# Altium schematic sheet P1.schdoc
size 297 x 209 mm; Symbol: Drawing-Symbol_A4; Company: 嘉立创EDA; Version: V1.0; Page Size: A4; @Project Name: esp32-c3-homekey+pen532; @Update Date: 2026-04-17; @Create Date: 2026-04-17; Device: Drawing-Symbol_A4; @Board Name: Board1; @Page Name: P1; @Create Time: 11:52:20; @Page Count: 1; @Page No: 1; @Schematic Name: Schematic1; @Update Time: 11:52:20; @Assembly Variant: Basic; Border: 1; Title Block Position: 3; Size: A4; Width: 1170; Height: 825; Region Start: 1; X Region Count: 6; Y Region Count: 4; Blade Width: 10; Title Block: 1
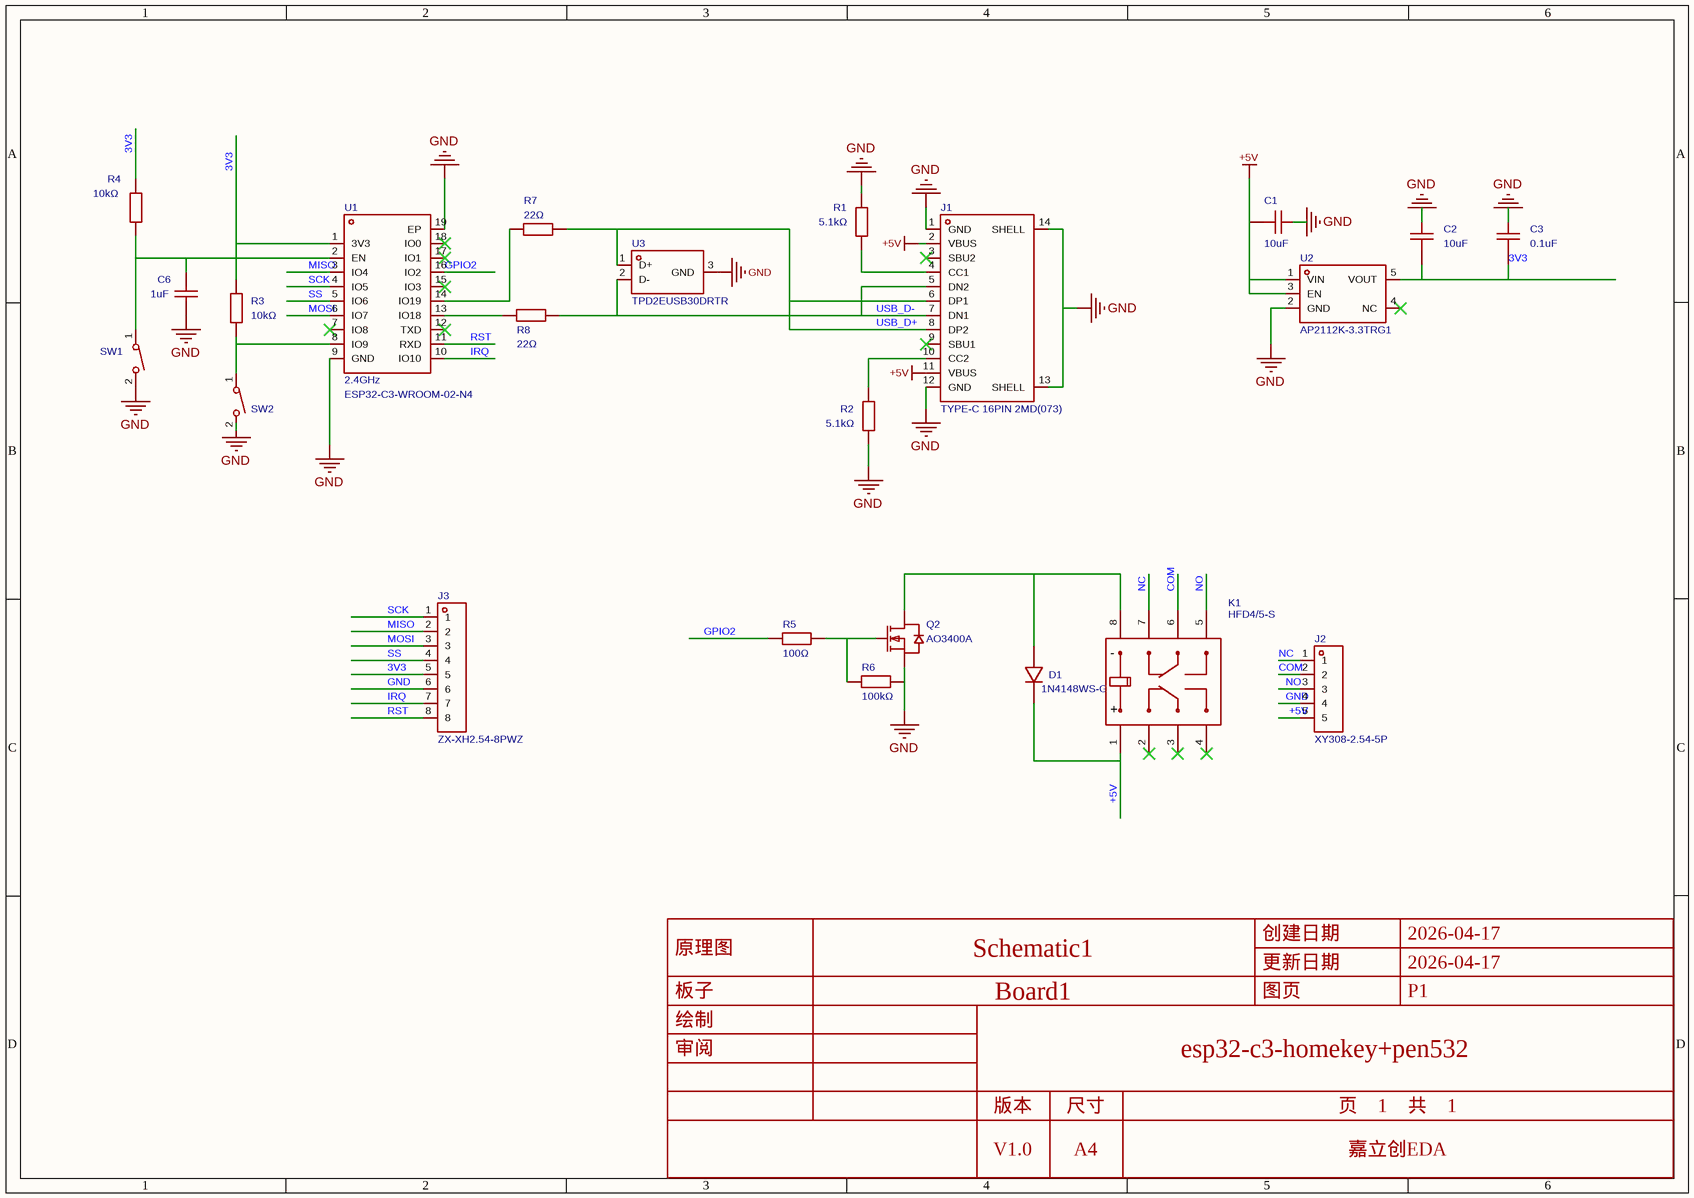
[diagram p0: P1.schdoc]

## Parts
C1  10uF  [C0805]
C2  10uF  [C0805]
C3  0.1uF  [C0805]
C6  1uF  [C0805]
D1  1N4148WS-G  [SOD-323_L1.7-W1.3-LS2.7-RD]
J1  TYPE-C 16PIN 2MD(073)  [USB-C-SMD_TYPE-C-6PIN-2MD-073]
J2  XY308-2.54-5P  [CONN-TH_XY308-2.54-5P]
J3  ZX-XH2.54-8PWZ  [CONN-TH_8P-P2.50_ZX-XH2.54-8PWZ]
K1  HFD4/5-S  [RELAY-SMD_HFD4-5-S]
Q2  AO3400A  [SOT-23-3_L2.9-W1.3-P1.90-LS2.4-BR]
R1  5.1kΩ  [R0805]
R2  5.1kΩ  [R0805]
R3  10kΩ  [R0805]
R4  10kΩ  [R0805]
R5  100Ω  [R0805]
R6  100kΩ  [R0805]
R7  22Ω  [R0603]
R8  22Ω  [R0603]
SW1  HX 3x4x2-2P-1.6N TACTILE SWITCH  [KEY-SMD_L4.0-W3.0-LS4.9-1]  (value not drawn)
SW2  HX 3x4x2-2P-1.6N TACTILE SWITCH  [KEY-SMD_L4.0-W3.0-LS4.9-1]  (value not drawn)
U1  2.4GHz  [BULETM-SMD_ESPRESSIF_ESP32-C3-WROOM-02-N4-4MB]
U2  AP2112K-3.3TRG1  [SOT-23-5_L2.9-W1.6-P0.95-LS2.8-BR]
U3  TPD2EUSB30DRTR  [SOT-723_L1.2-W0.8-P0.80-LS1.2-BR]

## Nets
+5V: C1.2 D1.1(-) J1.2(VBUS) J1.11(VBUS) J2.5 K1.1 U2.1(VIN) U2.3(EN)
GND: C1.1 C2.2 C3.1 C6.1 J1.1(GND) J1.12(GND) J1.13(SHELL) J1.14(SHELL) J2.4 J3.6 Q2.2(S) R1.2 R2.2 R6.2 SW1.2 SW2.2 U1.9(GND) U1.19(EP) U2.2(GND) U3.3(GND)
3V3: C2.1 C3.2 J3.5 R3.2 R4.2 U1.1(3V3) U2.5(VOUT)
COM: J2.2 K1.6
GPIO2: R5.1 U1.16(IO2)
IRQ: J3.7 U1.10(IO10)
MISO: J3.2 U1.3(IO4)
MOSI: J3.3 U1.6(IO7)
NC: J2.1 K1.7
NO: J2.3 K1.5
RST: J3.8 U1.11(RXD)
SCK: J3.1 U1.4(IO5)
SS: J3.4 U1.5(IO6)
USB_D+: J1.6(DP1) J1.8(DP2) R7.2 U3.1(D+)
USB_D-: J1.5(DN2) J1.7(DN1) R8.2 U3.2(D-)
NetC6_2: C6.2 R4.1 SW1.1 U1.2(EN)
NetD1_2: D1.2(+) K1.8 Q2.3(D)
NetJ1_4: J1.4(CC1) R1.1
NetJ1_10: J1.10(CC2) R2.1
NetQ2_1: Q2.1(G) R5.2 R6.1
NetR3_1: R3.1 SW2.1 U1.8(IO9)
NetR7_1: R7.1 U1.14(IO19)
NetR8_1: R8.1 U1.13(IO18)

Not connected (* = marked no-connect by the designer): J1 3(SBU2)* 9(SBU1)*; K1 2* 3* 4*; U1 7(IO8)* 12(TXD)* 15(IO3)* 17(IO1)* 18(IO0)*; U2 4(NC)*

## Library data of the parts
C1-C3 = CL21A106KAYNNNE_C15850: 容值:10uF;精度:±10%;额定电压:25V;温度系数:X5R;; Manufacturer: SAMSUNG(三星); 3D Model: 1ba041120af144c991958decab20d241; 3D Model Transform: 78.74,51.181,0,0,0,0,0,0.0005,0; Tolerance: ±10%; Voltage Rating: 25V; Temperature Coefficient: X5R; AddInBom: yes; ModelName: C0805_L2.0-W1.3-H1.3
C6 = CL21B105KBFNNNE: 容值:1uF;精度:±10%;额定电压:50V;温度系数:X7R;; Manufacturer: SAMSUNG(三星); 3D Model: 1ba041120af144c991958decab20d241; 3D Model Transform: 78.74,51.181,0,0,0,0,0,0.0005,0; Tolerance: ±10%; Voltage Rating: 50V; Temperature Coefficient: X7R; AddInBom: yes; ModelName: C0805_L2.0-W1.3-H1.3
D1 = 1N4148WS-G: 二极管配置:独立式;正向压降(Vf):1.25V@150mA;直流反向耐压(Vr):100V;整流电流:150mA;反向恢复时间(Trr):4ns;; Manufacturer: CJ(江苏长电/长晶); AddInBom: yes; ModelId: cb3f162a5497409a8a6cf33769e88f040819f05c4eef4c71ace90d822a990e87; ModelTransform: 102.362,50.197,0,0,0,0,0,0,0; Diode Configuration: 独立式; Voltage - DC Reverse(Vr): 100V; Current - Rectified: 150mA; Pd - Power Dissipation: 200mW; Reverse Leakage Current (Ir): 1uA@75V; Reverse Recovery Time (trr): 4ns; Non-Repetitive Peak Forward Surge Current: 2A
J1 = TYPE-C 16PIN 2MD(073): 连接器类型:Type-C;协议标准:-;公母:母;安装方式:卧贴;触点数量:16P;端口数量:1;额定电流 - 电源:3A;工作温度:-25℃~+85℃;; Manufacturer: SHOU HAN(首韩); 3D Model: 3a41b9ec9b654a0fad4d118405ec6290; 3D Model Transform: 351.9678,298.4246,0,0,0,0,0,-47.244,-35.433; Gender: 母; Number of Contacts: 16P; Number of Ports: 1; Current Rating-Power: 3A; Voltage Rating: 5V; Connect-Disconnect Life: 5千次; Detection color: 黑色; AddInBom: yes
J2 = XY308-2.54-5P: 结构:1x5P;间距:2.54mm;颜色:绿色;安装方式:直插;排数:1;每排PIN数:5;额定电流:6A;额定电压:150V;线规 - AWG:18~26;线规 - 平方毫米:1;工作温度:-;; Manufacturer: XINLAIYA(新莱亚); Add into BOM: yes; 3D Model: 19a24be1acf7462ab4ffe2d39b33f1bc; 3D Model Transform: 519.68794,255.905,0,0,0,0,0,-6.457,-137.795; Number of Positions or Pins: 1x5P; Pitch: 2.54mm; Number of PINs Per Row: 5; Screw Specification: M1.6; Current Rating: 6A; Voltage Rating (Max): 150V; Wire Gauge - AWG: 18~26; Wire Gauge - mm2: 1
J3 = ZX-XH2.54-8PWZ: 插针结构:1x8P;间距:2.5mm;安装方式:弯插;参考系列:XH;总PIN数:8P;排数:1;每排PIN数:8;行距:-;额定电流:3A;触头材质:黄铜;触头镀层:锡;工作温度:-25℃~+85℃;; Manufacturer: Megastar(兆星); AddInBom: yes; ModelId: 2313deb9a1954eec88de97710f9a8a070819f05c4eef4c71ace90d822a990e87; ModelTransform: 886.2187,300.7868,0,0,0,0,-0.002,-137.795,-133.858; Pins Structure: 1x8P; Pitch: 2.5mm; Reference Series: XH; Number of PINs Per Row: 8; Current Rating: 3A; Voltage Rating: 250V; Plastic Material: PA66; Flame Retardant Rating: UL94V-0; Z-Height of the Board: 5.9mm; X-Length of Bottom Edge on Board (Spacing Line): 22.5mm; Y-Width of Bottom Edge on Board: 7.32mm
K1 = HFD4/5-S: 线圈电压:5V;触点形式:两组转换:2C(双刀双掷-转换);触点容量(电阻负载):300mA@125VAC；1A@30VDC;最大切换电压:250V@AC；220V@DC;最大切换电流:2A;; Manufacturer: HF(宏发); Symbol: HFD4/5-S_C425975; AddInBom: yes; ModelId: 3a4f29bb16e8421f8a945af812fde40b0819f05c4eef4c71ace90d822a990e87; ModelName: SMD-8_L10.0-W6.5-H5.4-LS7.8-P2.2-3.2; ModelTransform: 393.7,307.086,0,0,0,0,0,0,0; Coil Voltage: 5V; Coil Rated Power: 140mW; Coil Resistance: 178Ω; Switching Current(Max): 2A; Operate Time: 3ms; Coil Type: 有极性-单线圈; Contact Resistance: 100mΩ
Q2 = AO3400A_C347475: 数量:1个N沟道;漏源电压(Vdss):30V;连续漏极电流(Id):5.8A;导通电阻(RDS(on)):17mΩ@10V;耗散功率(Pd):1.4W;阈值电压(Vgs(th)):1.1V@250uA;; Manufacturer: UMW(友台半导体); 3D Model: c62791f0466c4ae2a892c056b845b0ca; 3D Model Transform: 98.425,114.173,0,180,0,0,0.0005,-0.0005,0; Number: 1个N沟道; Drain to Source Voltage: 30V; Current - Continuous Drain(Id): 5.8A; Pd - Power Dissipation: 1.4W; Gate Charge(Qg): 9.7nC@4.5V; Input Capacitance(Ciss): 823pF; Reverse Transfer Capacitance (Crss@Vds): 77pF; Output Capacitance(Coss): 99pF; AddInBom: yes; ModelName: SOT-23-3P_L2.9-W1.3-H1.0-LS2.4-P0.95
R1 R2 = 0805W8F5101T5E: 电阻类型:厚膜电阻;阻值:5.1kΩ;精度:±1%;功率:125mW;工作电压:150V;温度系数:±100ppm/℃;; Manufacturer: UNI-ROYAL(厚声); 3D Model: 37a81e68749a4138bd2dfa6897b24b85; 3D Model Transform: 78.74,51.181,0,0,0,0,0,-0.0005,0; Tolerance: ±1%; Power(Watts): 125mW; Voltage-Supply(Max): 150V; AddInBom: yes; ModelName: R0805_L2.0-W1.3-H0.6
R3 R4 = 0805W8F1002T5E_C17414: 电阻类型:厚膜电阻;阻值:10kΩ;精度:±1%;功率:125mW;工作电压:150V;温度系数:±100ppm/℃;; Manufacturer: UNI-ROYAL(厚声); 3D Model: 37a81e68749a4138bd2dfa6897b24b85; 3D Model Transform: 78.74,51.181,0,0,0,0,0,-0.0005,0; Tolerance: ±1%; Power(Watts): 125mW; Voltage-Supply(Max): 150V; AddInBom: yes; ModelName: R0805_L2.0-W1.3-H0.6
R5 R6 = 0805W8F1003T5E: 电阻类型:厚膜电阻;阻值:100kΩ;精度:±1%;功率:125mW;工作电压:150V;温度系数:±100ppm/℃;; Manufacturer: UNI-ROYAL(厚声); Symbol: 0805W8F1003T5E_C149504; 3D Model: 37a81e68749a4138bd2dfa6897b24b85; 3D Model Transform: 78.74,51.181,0,0,0,0,0,-0.0005,0; Tolerance: ±1%; Power(Watts): 125mW; Voltage-Supply(Max): 150V; AddInBom: yes; ModelName: R0805_L2.0-W1.3-H0.6
R7 R8 = 0603WAF220JT5E: 电阻类型:厚膜电阻;阻值:22Ω;精度:±1%;功率:100mW;最大工作电压:75V;温度系数:±100ppm/℃;; Manufacturer: UNI-ROYAL(厚声); 3D Model: fc143cca1e79419f9cd78b61e9279f08; 3D Model Transform: 31.8897,63.7794,0,90,0,0,0,0,0; Tolerance: ±1%; Power(Watts): 100mW; Overload Voltage (Max): 75V; AddInBom: yes
SW1 SW2 = HX 3x4x2-2P-1.6N TACTILE SWITCH: 电路结构:单刀单掷;按钮形状:圆形按钮;作用力:1.6N;安装方式:立贴;开关长度:4mm;开关宽度:3mm;开关高度:2mm;带支架:不带支架;触点电流:50mA;额定电压:12V;带灯:无;工作寿命:10万次;; Manufacturer: hanxia(韩下); 3D Model: d4fce36ee1a0417eaaf0fe72bc7ffd98; 3D Model Transform: 188.976,114.173,0,0,0,0,0,0,-17.717; Circuit: 单刀单掷; Actuator Style: 圆形按钮; Operating Force: 1.6N; Switch Height: 2mm; with Bracket: 不带支架; Contact Current: 50mA; Voltage Rating: 12V; Actuator/Cap Color: 黑色; With Lamp: 无; Life: 10万次; AddInBom: yes; ModelName: KEY-SMD_L4.0-W3.0-LS4.9
U1 = ESP32-C3-WROOM-02-N4: 核心芯片:ESP32-C3芯片;频率:2.4GHz;天线形式:板载PCB天线;发射功率:20.5dBm;接收灵敏度:-105dBm;; Manufacturer: ESPRESSIF(乐鑫); Symbol: ESP32-C3-WROOM-02-N4(4MB); 3D Model: b84a3a07460a410dbd2d87addaa4e9c5; 3D Model Transform: 709.4474,787.4,0,0,0,0,-0.001,122.048,0; Wireless Standard: Bluetooth5.0; Interface Type: I2S；I2C；JTAG；UART；USB；SPI; Voltage - Supply: 3V~3.6V; Receive  Current: 82mA; Send  Current: 345mA; AddInBom: yes
U2 = AP2112K-3.3TRG1_C23380830: 输出类型:固定;工作电压:5.5V;输出电压:3.3V;输出电流:600mA;电源纹波抑制比(PSRR):75dB@(1kHz);输出极性:正极;; Manufacturer: TECH PUBLIC(台舟); 3D Model: 7ba65df16e7b4570af156e925f9c37fe; 3D Model Transform: 114.173,114.173,0,90,0,0,0,0,0; Output Type: 固定; Voltage - Supply: 5.5V; Output Voltage: 3.3V; Output Current: 600mA; Voltage Dropout: 320mV@(600mA); standby current: 10uA; Output Configuration: 正极; Number of Outputs: 1; AddInBom: yes
U3 = TPD2EUSB30DRTR_C5182099: 极性:单向;反向截止电压(Vrwm):5.5V;钳位电压:18V;击穿电压:7V;; Manufacturer: TECH PUBLIC(台舟); 3D Model: 8f70d69c83f742259d42411b19cb5a390819f05c4eef4c71ace90d822a990e87; 3D Model Transform: 47.244,47.244,0,0,0,0,0,0,0; Polarity: 单向; Reverse Stand-Off Voltage (Vrwm): 5.5V; Clamping Voltage: 18V; Voltage - Breakdown: 7V; Reverse Leakage Current (Ir): 100nA; level of protection: IEC 61000-4-4；IEC 61000-4-5；IEC 61000-4-2; Junction Capacitance: 0.4pF; AddInBom: yes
